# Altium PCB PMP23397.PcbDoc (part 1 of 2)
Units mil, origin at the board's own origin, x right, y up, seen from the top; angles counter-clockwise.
Board outline 1800 x 1800 mil, 2 copper layers (Top Layer, Bottom Layer), stack 62 mil thick; 47 components, 18 nets, 94 pads, 33 vias.
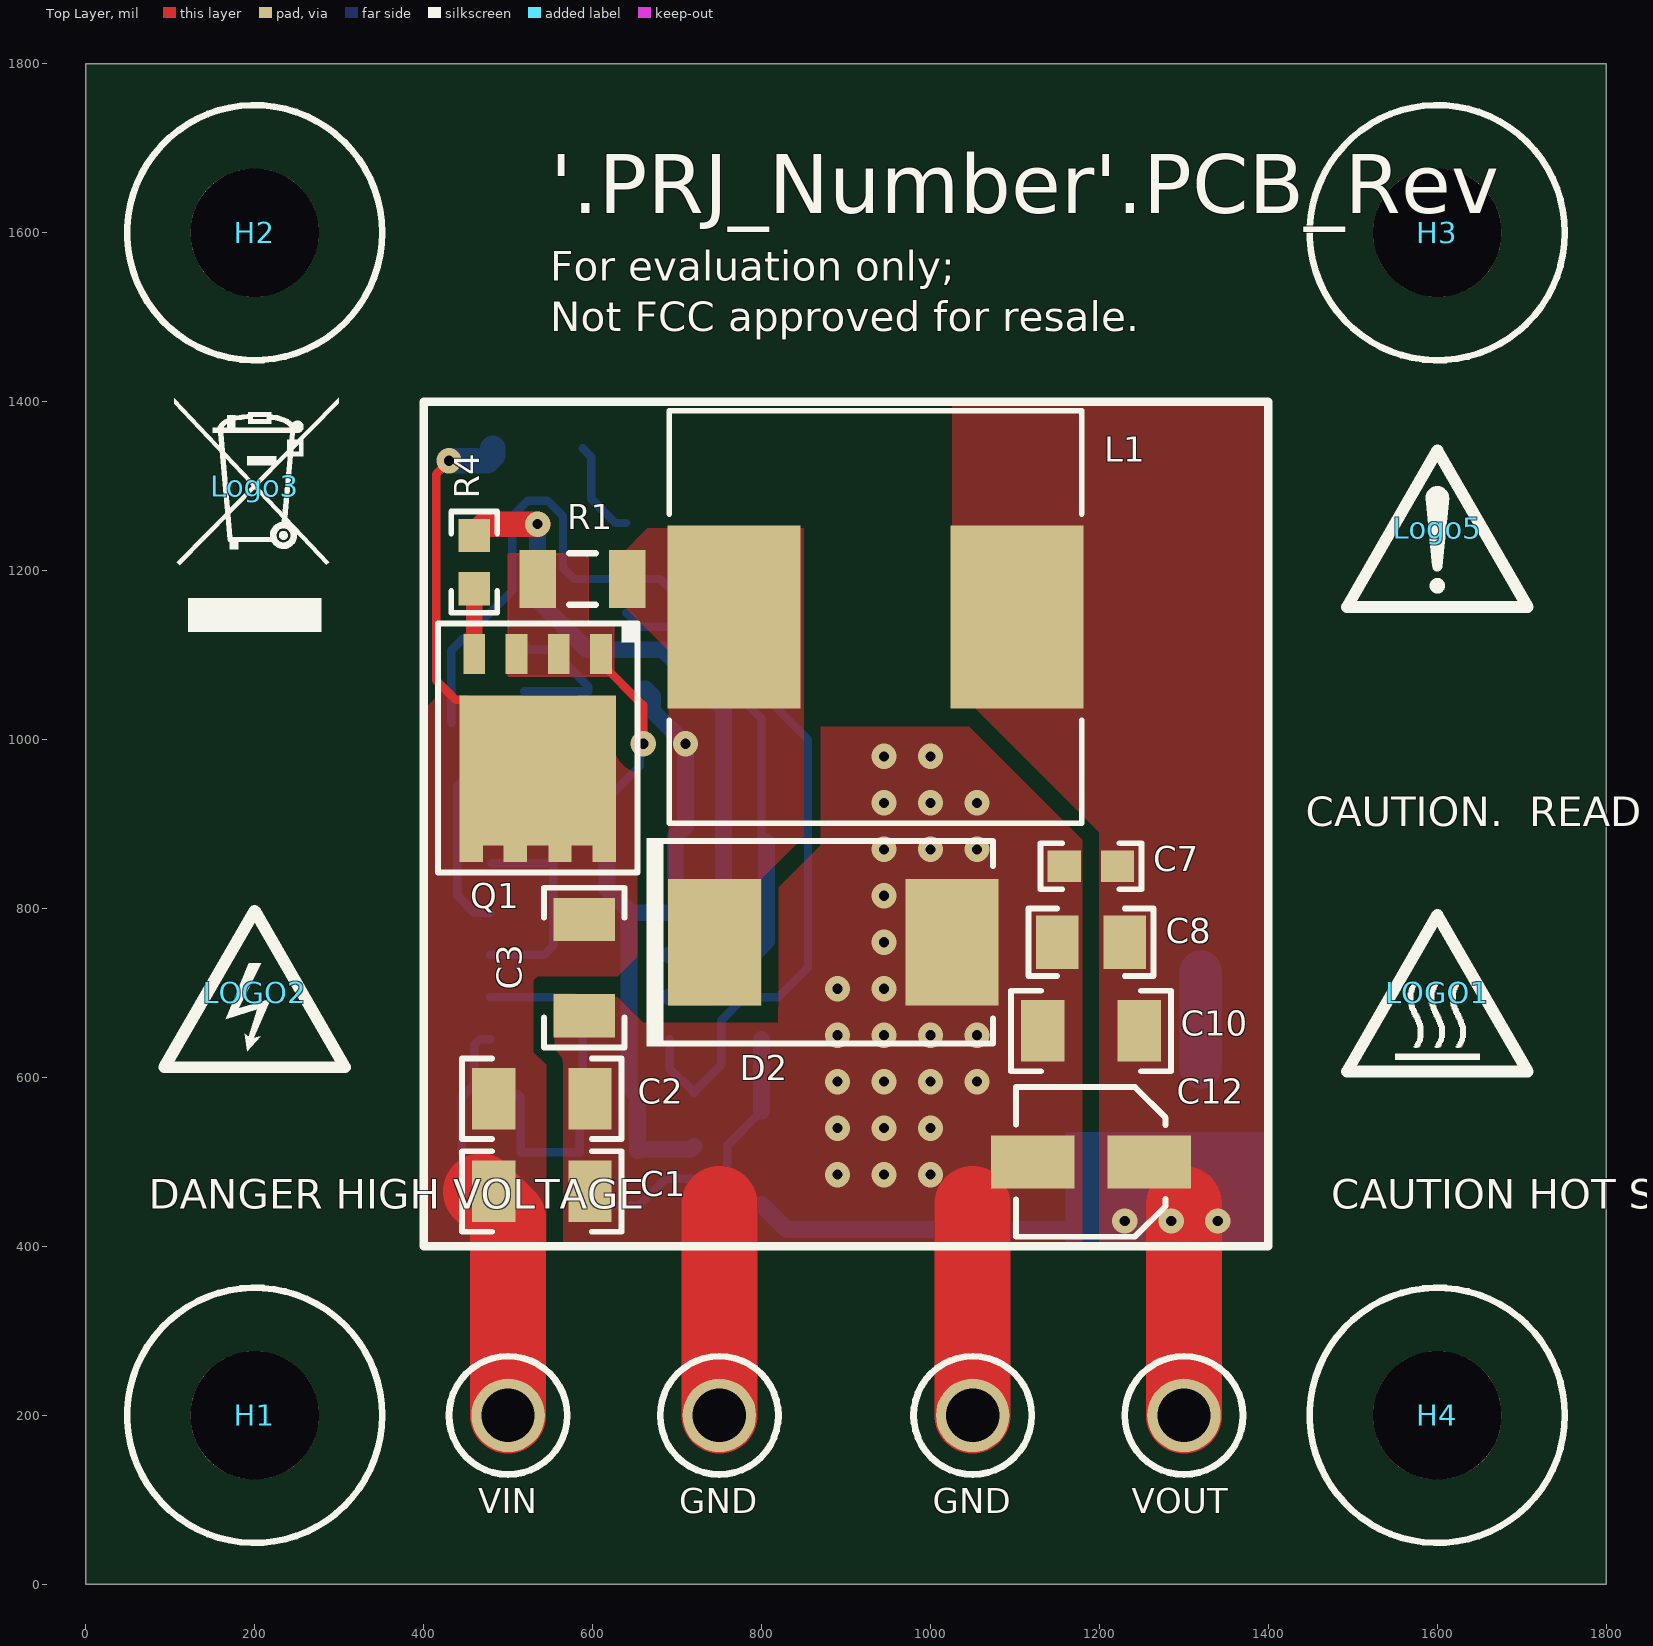
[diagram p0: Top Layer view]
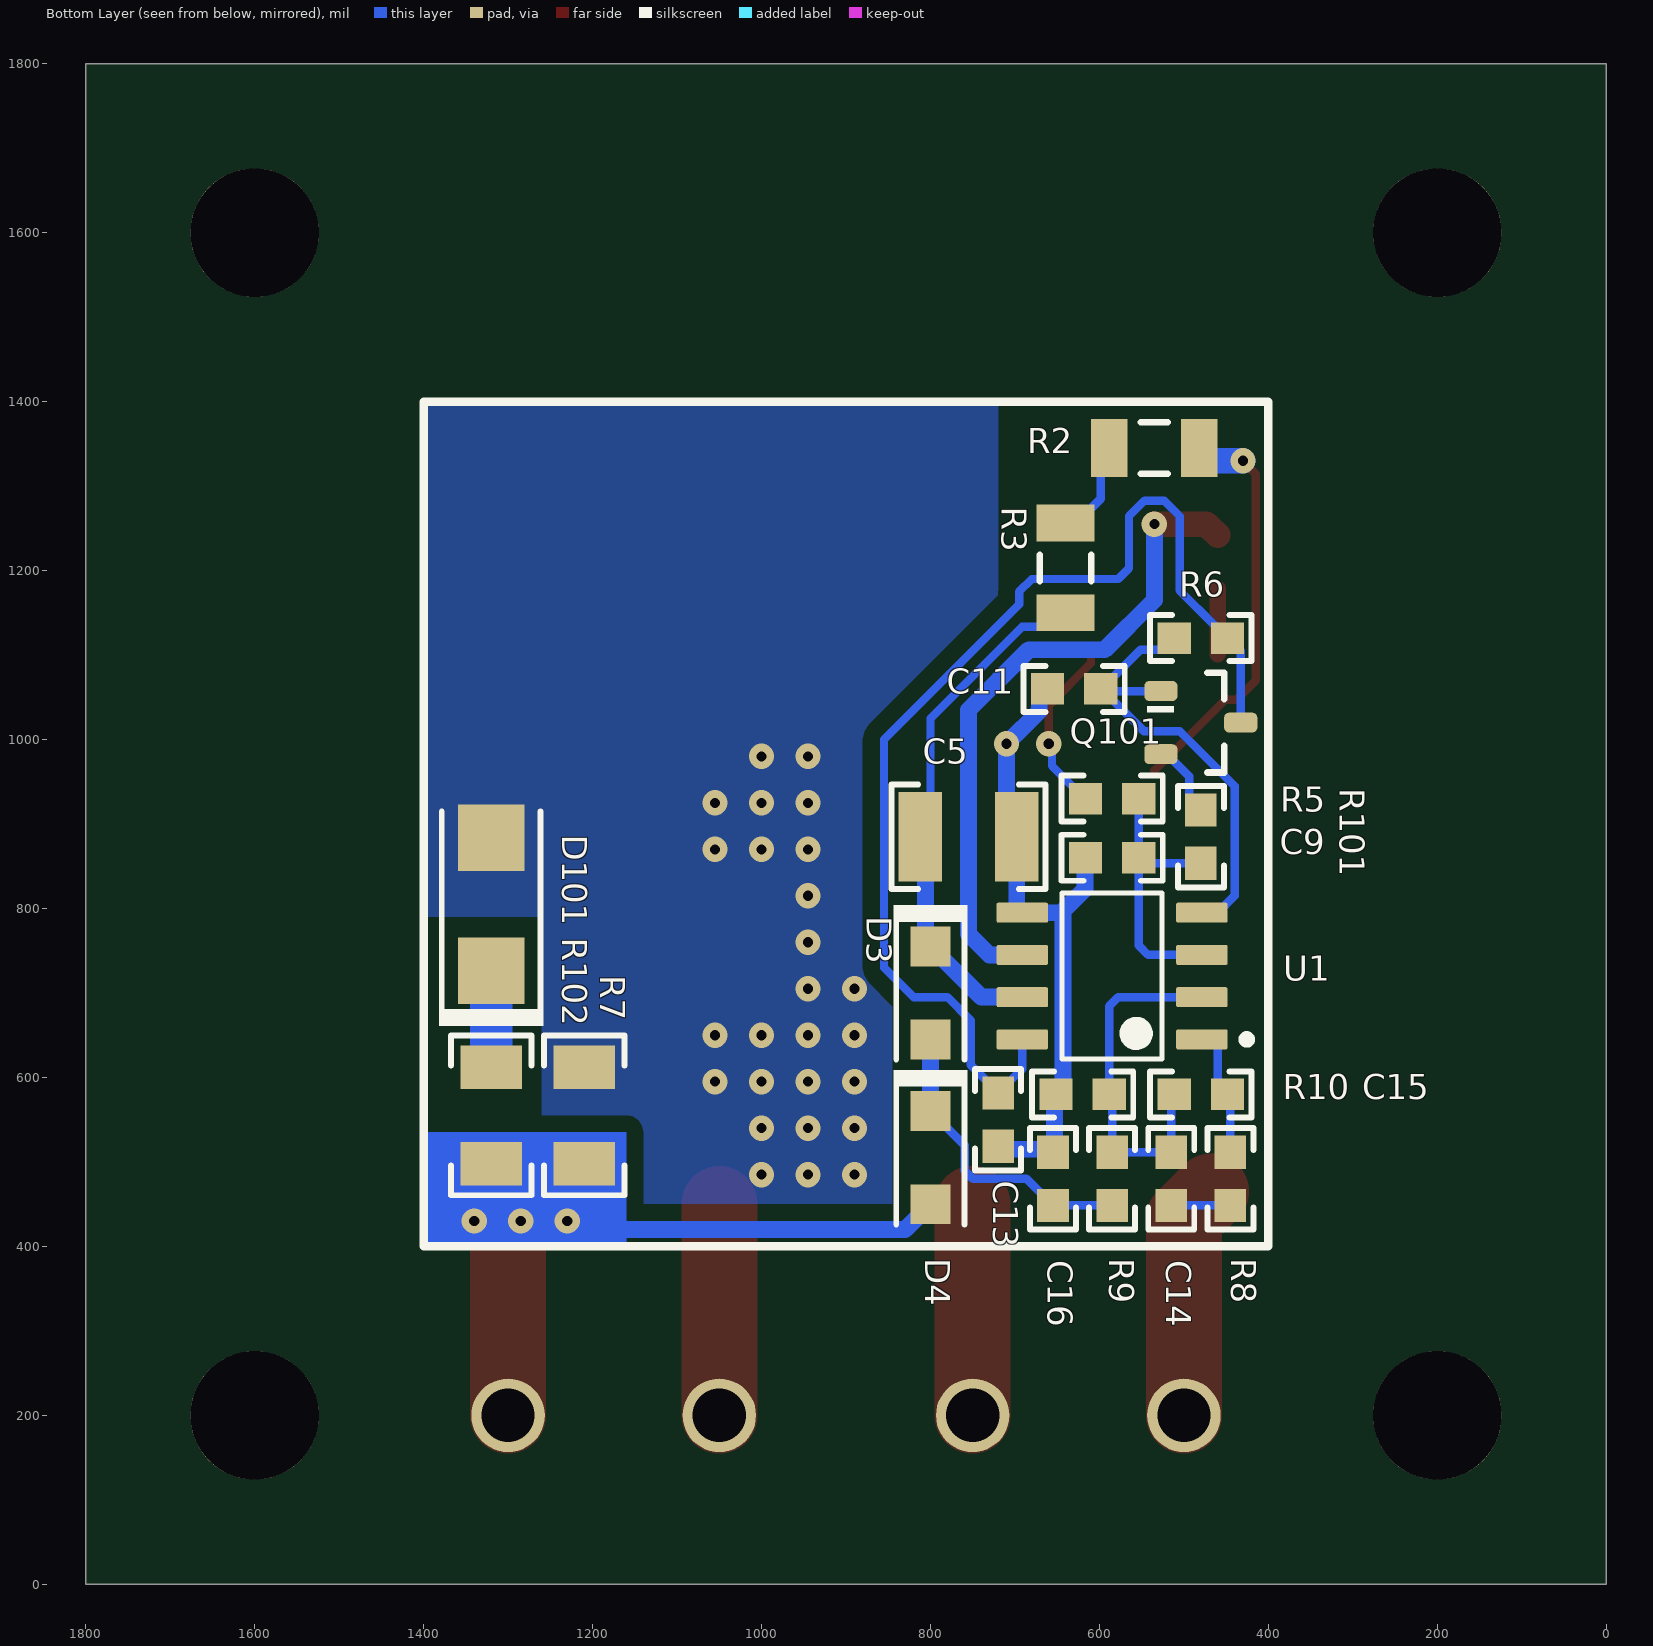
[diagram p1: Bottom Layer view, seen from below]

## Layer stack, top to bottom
Top Solder: solder mask 0.4, Solder Resist, Dk 3.5
Top Layer: signal copper 1.4
Dielectric1: core 59.2, FR-4 High Tg, Dk 4.8
Bottom Layer: signal copper 1.4
Bottom Solder: solder mask 0.4, Solder Resist, Dk 3.5

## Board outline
0,0 0,1800 1800,1800 1800,0

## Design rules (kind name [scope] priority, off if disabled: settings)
AcuteAngle [All] p1: minimum=4.50000000000000E+0001 checktracksonly=FALSE
AssemblyTestPointUsage [All] p1: valid=2
BoardOutlineClearance BoardOutlineClearance_MountingHoles [OnCopper and InComponentClass('Mounting Holes')] p1: gap=25 ignorepadtopadclearanceinfootprint=FALSE
BoardOutlineClearance BoardOutlineClearance_Poly [OnCopper and InPoly] p2: gap=25 ignorepadtopadclearanceinfootprint=FALSE
BoardOutlineClearance [OnCopper and Not InComponentClass('Logo') and not InComponentClass('FiducialMark') and not InRegion(1000,500,4000,800)] p3: gap=25 ignorepadtopadclearanceinfootprint=FALSE
Clearance Clearance_2 [InNetClass('HV') vs Not InNetClass('HV')] p1: gap=60 ignorepadtopadclearanceinfootprint=FALSE
Clearance Clearance_1 [InNetClass('MV') vs Not InNetClass('MV')] p2: gap=30 ignorepadtopadclearanceinfootprint=FALSE
Clearance Clearance_Keepouts [((IsTrack Or IsArc) And Not InPoly) And IsFree and IsKeepOut vs ((IsTrack Or IsArc) And Not InPoly) And IsFree and IsKeepOut] p3: gap=0 ignorepadtopadclearanceinfootprint=FALSE
Clearance Clearance_BoardEdge_MountingHoles [OnCopper and InComponentClass('Mounting Holes') vs IsKeepOut] p4: gap=40 ignorepadtopadclearanceinfootprint=FALSE except(0: Arc-Hole Track-Hole SMDPad-Hole THPad-Hole Via-Hole Fill-Hole Poly-Hole Region-Hole Text-Hole)
Clearance Clearance_BoardEdge_Poly [OnCopper and InPoly vs IsKeepOut] p5: gap=50 ignorepadtopadclearanceinfootprint=FALSE except(0: Arc-Hole Track-Hole SMDPad-Hole THPad-Hole Via-Hole Fill-Hole Poly-Hole Region-Hole Text-Hole)
Clearance Clearance_BoardEdge [OnCopper and Not InComponentClass('Logo') and not InComponentClass('FiducialMark') and not InRegion(1000,500,4000,800) and Not IsKeepout vs IsKeepOut] p6: gap=50 ignorepadtopadclearanceinfootprint=FALSE
Clearance Clearance_Poly [InPolygon] p7: gap=20 ignorepadtopadclearanceinfootprint=FALSE except(0: Arc-Hole Track-Hole SMDPad-Hole THPad-Hole Via-Hole Fill-Hole Poly-Hole Region-Hole Text-Hole)
Clearance [All] p8: gap=7.87 ignorepadtopadclearanceinfootprint=FALSE except(0: Arc-Hole Track-Hole SMDPad-Hole THPad-Hole Via-Hole Fill-Hole Poly-Hole Region-Hole Text-Hole)
ComponentClearance ComponentClearance_MountingHoles_FiducialMarks [InComponentClass('Mounting Holes') vs InComponentClass('FiducialMark')] p1: gap=20 collisioncheckmode=3 verticalgap=10 showdistances=FALSE
ComponentClearance ComponentClearance_Shunt [InComponentClass('Header') vs InComponentClass('Shunt')] p2: gap=0 collisioncheckmode=3 verticalgap=0 showdistances=FALSE
ComponentClearance ComponentClearance_Logo [InComponentClass('Logo')] p3: gap=5 collisioncheckmode=3 verticalgap=10 showdistances=FALSE
ComponentClearance ComponentClearance_ScrewToNut [(HasFootprint('NY PMS 440 0025 PH')) vs (HasFootprint('Keystone_1902C'))] p4: gap=20 collisioncheckmode=3 verticalgap=100000 showdistances=FALSE
ComponentClearance ComponentClearance_MountingHoles [InComponentClass('Mounting Holes')] p5: gap=20 collisioncheckmode=3 verticalgap=10 showdistances=FALSE
ComponentClearance ComponentClearance_SmallPassives [HasFootprint('0201*') or HasFootprint('0402*') or HasFootprint('0508') or HasFootprint('0603*') or HasFootprint('0612') or HasFootprint('0805*') or HasFootprint('0815*') or HasFootprint('0830*') or HasFootprint('1206*') or HasFootprint('1210*') or HasFootprint('1808*') or HasFootprint('1812*') or HasFootprint('1825*') or HasFootprint('2010*') or HasFootprint('2220*') or HasFootprint('2225*') or HasFootprint('2512*') or HasFootprint('2728*') or HasFootprint('3518*') vs HasFootprint('0201*') or HasFootprint('0402*') or HasFootprint('0508') or HasFootprint('0603*') or HasFootprint('0612') or HasFootprint('0805*') or HasFootprint('0815*') or HasFootprint('0830*') or HasFootprint('1206*') or HasFootprint('1210*') or HasFootprint('1808*') or HasFootprint('1812*') or HasFootprint('1825*') or HasFootprint('2010*') or HasFootprint('2220*') or HasFootprint('2225*') or HasFootprint('2512*') or HasFootprint('2728*') or HasFootprint('3518*')] p6: gap=20 collisioncheckmode=3 verticalgap=20 showdistances=FALSE
ComponentClearance ComponentClearance_THtoSMT [IsThruComponent vs IsSMTComponent] p7: gap=10 collisioncheckmode=3 verticalgap=10 showdistances=FALSE
ComponentClearance ComponentClearance_THtoTH [IsThruComponent vs IsThruComponent] p8: gap=10 collisioncheckmode=3 verticalgap=10 showdistances=FALSE
ComponentClearance [All] p9: gap=10 collisioncheckmode=3 verticalgap=10 showdistances=FALSE
DiffPairsRouting [All] p1: maxlimit=100 minlimit=10 mostfreqgap=10 toplayer_minwidth=15 toplayer_maxwidth=15 toplayer_prefwidth=15 bottomlayer_minwidth=15 bottomlayer_maxwidth=15 bottomlayer_prefwidth=15 maxuncoupledlength=1000
FabricationTestPointUsage TestPointUsage [All] p1: valid=2 allowmultiple=FALSE
FabricationTestpoint Testpoint [All] p1: side=3 testpointundercomponent=TRUE minsize=40 maxsize=100 preferedsize=60 minholesize=0 maxholesize=40 preferedholesize=32 testpointgrid=1 allowsidetop=TRUE allowsidebottom=TRUE usegrid=TRUE gridtolerance=0.01
FanoutControl Fanout_LCC [IsLCC] p1: bgadir=Out bgaviamode=Centered fanoutstyle=Auto fanoutdirection=Alternating viagrid=1 // Fanout_LCC (Default Rule)
FanoutControl Fanout_BGA [IsBGA] p2: bgadir=Out bgaviamode=Centered fanoutstyle=Auto fanoutdirection=Alternating viagrid=1 // Fanout_BGA (Default Rule)
FanoutControl Fanout_Default [All] p4: bgadir=Out bgaviamode=Centered fanoutstyle=Auto fanoutdirection=Alternating viagrid=1 // Fanout_Default (Default Rule)
FanoutControl Fanout_Small [(CompPinCount < 5)] p5: bgadir=Out bgaviamode=Centered fanoutstyle=Auto fanoutdirection=OutThenIn viagrid=1 // Fanout_Small (Default Rule)
Height [All] p1: minheight=0 maxheight=3000 prefheight=500
HoleSize [All] p1: absolutevalues=TRUE maxlimit=251 minlimit=7.87 maxpercent=80.000 minpercent=20.000
MinimumAnnularRing MinimumAnnularRing_ThermalPadVias [IsVia and InAnyComponent] p1: minimumring=5.91
MinimumAnnularRing [All] p2: minimumring=8
MinimumSolderMaskSliver MinimumSolderMaskSliver_Logo [InComponentClass('Logo') vs InComponentClass('Logo')] p1: minsoldermaskwidth=0.7
MinimumSolderMaskSliver [All] p2: minsoldermaskwidth=3.94
PlaneConnect [All] p1: planeconnectstyle=Direct reliefexpansion=10 reliefentries=4 reliefconductorwidth=10 reliefairgap=10
PolygonConnect PolygonConnect_15 [All vs IsNamedPolygon('C109_2') Or  IsNamedPolygon('C107_2') Or  IsNamedPolygon('HV') Or  IsNamedPolygon('Q203_5') Or  IsNamedPolygon('C107_2') Or  IsNamedPolygon('HS') Or  IsNamedPolygon('Q201_5') Or  IsNamedPolygon('Q203_5') Or  IsNamedPolygon('C106_2') Or  IsNamedPolygon('C108_2') Or  IsNamedPolygon('Vout') Or  IsNamedPolygon('Q203_5') Or  IsNamedPolygon('C108_2') Or  IsNamedPolygon('C113_2') Or  IsNamedPolygon('Q203_5') Or  IsNamedPolygon('Q201_5') Or  IsNamedPolygon('C107_2') Or  IsNamedPolygon('C102_1') Or  IsNamedPolygon('SGND') Or  IsNamedPolygon('GND') Or  IsNamedPolygon('SGND') Or  IsNamedPolygon('GND') Or  IsNamedPolygon('IN+') Or  IsNamedPolygon('IN+') Or  IsNamedPolygon('Q201_5') Or  IsNamedPolygon('Q201_5') Or  IsNamedPolygon('SGND') Or  IsNamedPolygon('SGND') Or  IsNamedPolygon('Vout') Or  IsNamedPolygon('Vout') Or  IsNamedPolygon('IN+') Or  IsNamedPolygon('GND') Or  IsNamedPolygon('IN+') Or  IsNamedPolygon('GND')] p1: connectstyle=Direct reliefconductorwidth=10 reliefentries=4 polygonreliefangle="90 Angle" airgapwidth=10
PolygonConnect PolygonConnect_14 [All vs IsNamedPolygon('C106_2') Or  IsNamedPolygon('C107_2') Or  IsNamedPolygon('C107_2') Or  IsNamedPolygon('C107_2') Or  IsNamedPolygon('C102_1') Or  IsNamedPolygon('Q203_5') Or  IsNamedPolygon('Vout') Or  IsNamedPolygon('Q203_5') Or  IsNamedPolygon('Q203_5') Or  IsNamedPolygon('Q201_5') Or  IsNamedPolygon('C108_2') Or  IsNamedPolygon('Q203_5') Or  IsNamedPolygon('HS') Or  IsNamedPolygon('HV') Or  IsNamedPolygon('C108_2') Or  IsNamedPolygon('Q201_5') Or  IsNamedPolygon('C109_2') Or  IsNamedPolygon('Q201_5') Or  IsNamedPolygon('Q201_5') Or  IsNamedPolygon('C113_2')] p2: connectstyle=Direct reliefconductorwidth=10 reliefentries=4 polygonreliefangle="90 Angle" airgapwidth=10
PolygonConnect PolygonConnect_13 [All vs IsNamedPolygon('C102_1') Or  IsNamedPolygon('HV') Or  IsNamedPolygon('C107_2') Or  IsNamedPolygon('C109_2') Or  IsNamedPolygon('C107_2') Or  IsNamedPolygon('C108_2') Or  IsNamedPolygon('C106_2') Or  IsNamedPolygon('C108_2') Or  IsNamedPolygon('C113_2') Or  IsNamedPolygon('C107_2')] p3: connectstyle=Direct reliefconductorwidth=10 reliefentries=4 polygonreliefangle="90 Angle" airgapwidth=10
PolygonConnect PolygonConnect_12 [All vs IsNamedPolygon('C107_2') Or  IsNamedPolygon('C113_2') Or  IsNamedPolygon('C106_2') Or  IsNamedPolygon('C107_2') Or  IsNamedPolygon('C107_2') Or  IsNamedPolygon('C102_1')] p4: connectstyle=Direct reliefconductorwidth=10 reliefentries=4 polygonreliefangle="90 Angle" airgapwidth=10
PolygonConnect PolygonConnect_11 [All vs IsNamedPolygon('C106_2') Or  IsNamedPolygon('C102_1') Or  IsNamedPolygon('C107_2') Or  IsNamedPolygon('C107_2') Or  IsNamedPolygon('C107_2')] p5: connectstyle=Direct reliefconductorwidth=10 reliefentries=4 polygonreliefangle="90 Angle" airgapwidth=10
PolygonConnect PolygonConnect_10 [All vs IsNamedPolygon('C106_2')] p6: connectstyle=Direct reliefconductorwidth=10 reliefentries=4 polygonreliefangle="90 Angle" airgapwidth=10
PolygonConnect PolygonConnect_9 [All vs IsNamedPolygon('C11_1') Or  IsNamedPolygon('Vin') Or  IsNamedPolygon('Vin') Or  IsNamedPolygon('5V') Or  IsNamedPolygon('D6_2') Or  IsNamedPolygon('Q3_3') Or  IsNamedPolygon('GND2') Or  IsNamedPolygon('GND2') Or  IsNamedPolygon('GND') Or  IsNamedPolygon('Q3_4') Or  IsNamedPolygon('12V5') Or  IsNamedPolygon('GND') Or  IsNamedPolygon('12V5') Or  IsNamedPolygon('D3_1')] p7: connectstyle=Direct reliefconductorwidth=10 reliefentries=4 polygonreliefangle="90 Angle" airgapwidth=10
PolygonConnect PolygonConnect_8 [All vs IsNamedPolygon('C11_1') Or  IsNamedPolygon('Vin') Or  IsNamedPolygon('12V5') Or  IsNamedPolygon('Q3_3') Or  IsNamedPolygon('GND2') Or  IsNamedPolygon('GND2') Or  IsNamedPolygon('5V') Or  IsNamedPolygon('Q3_4') Or  IsNamedPolygon('12V5')] p8: connectstyle=Direct reliefconductorwidth=10 reliefentries=4 polygonreliefangle="90 Angle" airgapwidth=10
PolygonConnect PolygonConnect_7 [All vs IsNamedPolygon('GND2') Or  IsNamedPolygon('GND2') Or  IsNamedPolygon('5V') Or  IsNamedPolygon('12V5') Or  IsNamedPolygon('12V5') Or  IsNamedPolygon('C11_1')] p9: connectstyle=Direct reliefconductorwidth=10 reliefentries=4 polygonreliefangle="90 Angle" airgapwidth=10
PolygonConnect PolygonConnect_6 [All vs IsNamedPolygon('GND2') Or  IsNamedPolygon('SGND') Or  IsNamedPolygon('GND1') Or  IsNamedPolygon('C901_1') Or  IsNamedPolygon('SGND') Or  IsNamedPolygon('GND2') Or  IsNamedPolygon('GND1')] p10: connectstyle=Direct reliefconductorwidth=10 reliefentries=4 polygonreliefangle="90 Angle" airgapwidth=10
PolygonConnect PolygonConnect_5 [All vs IsNamedPolygon('GND1') Or  IsNamedPolygon('GND1')] p11: connectstyle=Direct reliefconductorwidth=10 reliefentries=4 polygonreliefangle="90 Angle" airgapwidth=10
PolygonConnect PolygonConnect_4 [All vs IsNamedPolygon('C21_1') Or  IsNamedPolygon('C5_1') Or  IsNamedPolygon('C12_2') Or  IsNamedPolygon('C2_2') Or  IsNamedPolygon('C13_1') Or  IsNamedPolygon('C28_1') Or  IsNamedPolygon('C6_1') Or  IsNamedPolygon('GND') Or  IsNamedPolygon('GND2') Or  IsNamedPolygon('C14_1') Or  IsNamedPolygon('C13_1') Or  IsNamedPolygon('Q1_3') Or  IsNamedPolygon('C14_1') Or  IsNamedPolygon('C5_1') Or  IsNamedPolygon('GND2') Or  IsNamedPolygon('C28_1') Or  IsNamedPolygon('D5_2') Or  IsNamedPolygon('D6_2') Or  IsNamedPolygon('D2_1') Or  IsNamedPolygon('C12_2') Or  IsNamedPolygon('D2_1') Or  IsNamedPolygon('C4_1') Or  IsNamedPolygon('C4_1') Or  IsNamedPolygon('C2_2') Or  IsNamedPolygon('GND') Or  IsNamedPolygon('C33_1') Or  IsNamedPolygon('C9_1')] p12: connectstyle=Direct reliefconductorwidth=10 reliefentries=4 polygonreliefangle="90 Angle" airgapwidth=10
PolygonConnect PolygonConnect_3 [All vs IsNamedPolygon('C28_1') Or  IsNamedPolygon('C12_2') Or  IsNamedPolygon('C28_1') Or  IsNamedPolygon('C9_1') Or  IsNamedPolygon('D5_2') Or  IsNamedPolygon('C12_2') Or  IsNamedPolygon('C2_2') Or  IsNamedPolygon('C14_1') Or  IsNamedPolygon('C4_1') Or  IsNamedPolygon('C14_1') Or  IsNamedPolygon('D6_2') Or  IsNamedPolygon('GND2') Or  IsNamedPolygon('Q1_3') Or  IsNamedPolygon('C5_1') Or  IsNamedPolygon('D2_1') Or  IsNamedPolygon('C4_1') Or  IsNamedPolygon('C13_1') Or  IsNamedPolygon('C5_1') Or  IsNamedPolygon('C13_1') Or  IsNamedPolygon('C33_1') Or  IsNamedPolygon('D2_1') Or  IsNamedPolygon('GND') Or  IsNamedPolygon('GND') Or  IsNamedPolygon('GND2') Or  IsNamedPolygon('C2_2') Or  IsNamedPolygon('C6_1') Or  IsNamedPolygon('C21_1')] p13: connectstyle=Direct reliefconductorwidth=10 reliefentries=4 polygonreliefangle="90 Angle" airgapwidth=10
PolygonConnect PolygonConnect_2 [All vs IsNamedPolygon('C21_1') Or  IsNamedPolygon('C4_1') Or  IsNamedPolygon('D5_2') Or  IsNamedPolygon('C5_1') Or  IsNamedPolygon('C14_1') Or  IsNamedPolygon('C13_1') Or  IsNamedPolygon('C4_1') Or  IsNamedPolygon('C33_1') Or  IsNamedPolygon('C12_2') Or  IsNamedPolygon('D2_1') Or  IsNamedPolygon('C2_2') Or  IsNamedPolygon('C28_1') Or  IsNamedPolygon('C12_2') Or  IsNamedPolygon('D2_1') Or  IsNamedPolygon('C5_1') Or  IsNamedPolygon('Q1_3') Or  IsNamedPolygon('GND') Or  IsNamedPolygon('D6_2') Or  IsNamedPolygon('C6_1') Or  IsNamedPolygon('C2_2') Or  IsNamedPolygon('C14_1') Or  IsNamedPolygon('C28_1') Or  IsNamedPolygon('C13_1') Or  IsNamedPolygon('C9_1') Or  IsNamedPolygon('GND')] p14: connectstyle=Direct reliefconductorwidth=10 reliefentries=4 polygonreliefangle="90 Angle" airgapwidth=10
PolygonConnect PolygonConnect_1 [All vs IsNamedPolygon('C28_1') Or  IsNamedPolygon('D5_2') Or  IsNamedPolygon('C5_1') Or  IsNamedPolygon('C5_1') Or  IsNamedPolygon('D2_1') Or  IsNamedPolygon('C21_1') Or  IsNamedPolygon('C9_1') Or  IsNamedPolygon('C4_1') Or  IsNamedPolygon('C14_1') Or  IsNamedPolygon('C28_1') Or  IsNamedPolygon('C6_1') Or  IsNamedPolygon('C12_2') Or  IsNamedPolygon('C33_1') Or  IsNamedPolygon('C4_1') Or  IsNamedPolygon('C13_1') Or  IsNamedPolygon('C12_2') Or  IsNamedPolygon('D6_2') Or  IsNamedPolygon('C2_2') Or  IsNamedPolygon('C14_1') Or  IsNamedPolygon('D2_1') Or  IsNamedPolygon('C2_2') Or  IsNamedPolygon('C13_1')] p15: connectstyle=Direct reliefconductorwidth=10 reliefentries=4 polygonreliefangle="90 Angle" airgapwidth=10
PolygonConnect [All] p16: connectstyle=Direct reliefconductorwidth=10 reliefentries=4 polygonreliefangle="90 Angle" airgapwidth=10
RoutingVias ThermalPadVias [IsVia and InAnyComponent] p1: holewidth=7.87 width=19.68 viastyle="Through Hole" minholewidth=7.87 minwidth=19.68 maxholewidth=12.99 maxwidth=23.62
RoutingVias [All] p2: holewidth=16 width=34 viastyle="Through Hole" minholewidth=7.87 minwidth=20 maxholewidth=40 maxwidth=65
SilkToBoardRegionClearance [Not ((IsComment or IsDesignator) And (Hide <> 'False')) and not InRegion(1000,500,4000,800)] p1:
SilkToSilkClearance SilkToSilkClearance_Pb-FreeLogo [(HasFootprint('Pb-Free_Overlay_Medium') OR HasFootprint('Pb-Free_Overlay_Small')) vs (HasFootprint('Pb-Free_Overlay_Medium') OR HasFootprint('Pb-Free_Overlay_Small'))] p1: silktosilkclearance=0
SilkToSilkClearance [All] p2: silktosilkclearance=4
SilkToSolderMaskClearance SilkToComponentPadClearance [IsPad and InAnycomponent] p1: minsilkscreentomaskgap=5 clearancetoexposedcopper=TRUE
SilkToSolderMaskClearance "Silk to Solder Mask Opening" [All] p2: minsilkscreentomaskgap=4 clearancetoexposedcopper=FALSE
SolderMaskExpansion [All] p1: expansion=1.97 istentingtop=FALSE
Width [All] p1: maxlimit=100 minlimit=6 preferedwidth=10 checkconnectedcopper=TRUE
14 further rules are at their usual default settings.

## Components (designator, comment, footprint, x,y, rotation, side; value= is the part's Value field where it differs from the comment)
C1 "CGA5L3X7T2E224K160AE" 1206 540,465 r0 top value=0.22uF
C2 "CGA5L3X7T2E224K160AE" 1206 540,575 r0 top value=0.22uF
C3 "CGA5L3X7T2E224K160AE" 1206 590,730 r270 top value=0.22uF
C5 "GRM32ER61E226KE15L" 1210_270 755,885 r180 bottom value=22uF
C7 "GRM188R71E224KA88D" 0603 1190,850 r180 top value=0.22uF
C8 "GRM21BR71E225KA73L" 0805_HV 1190,760 r180 top value=2.2uF
C9 "GRM1885C1H101JA01D" 0603 585,860 r180 bottom value=100pF
C10 "GRM31CR71E106MA12L" 1206 1190,655 r180 top value=10uF
C11 "GRM188R71E222KA01D" 0603 630,1060 r0 bottom value=2200pF
C12 "EEE-FK1C220UR" SM_RADIAL_B 1190,500 r180 top value=22uF
C13 "GRM188R71E224KA88D" 0603 720,550 r270 bottom value=0.22uF
C14 "GRM188R71E224KA88D" 0603 515,480 r270 bottom value=0.22uF
C15 "GRM188R71E222KA01D" 0603 480,580 r0 bottom value=2200pF
C16 "GRM188R71E224KA88D" 0603 655,480 r270 bottom value=0.22uF
D2 "ES3G-E3/57T" SMC 885,760 r0 top value=400V
D3 "BAS21H,115" SOD-123F 800,700 r270 bottom value=200V
D4 "BAS21H,115" SOD-123F 800,505 r270 bottom value=200V
D101 "SMAJ14A" SMA 1320,805 r90 bottom value=14V
GND "5011" Keystone5011 1050,200 r0 top
GND "5011" Keystone5011 750,200 r0 top
H1 "4824" KEYSTONE_4824 200,200 r0 top
H2 "4824" KEYSTONE_4824 200,1600 r0 top
H3 "4824" KEYSTONE_4824 1600,1600 r0 top
H4 "4824" KEYSTONE_4824 1600,200 r0 top
L1 "MSS1278H-684KLB" MSS1278 935,1145 r0 top value=680uH
LOGO1 "CAUTION HOT SURFACE" IEC_HotSurface_Small 1600,700 r0 top
LOGO2 "DANGER HIGH VOLTAGE" IEC_HighVoltage_Small 200,700 r0 top
Logo3 "WEEE logo" WEEE_Minimum 200,1300 r0 top
Logo4 "FCC disclaimer" FCC_disclaimer 990,2010 r0 top
Logo5 "CAUTION.  READ USER GUIDE BEFORE USE" IEC_Caution_Small 1600,1250 r0 top
Q1 "BSC16DN25NS3 G" PG-TDSON-8 535,990 r270 top value=250V
Q101 "MMBT2222A" SOT-23 480,1020 r180 bottom value="40 V"
R1 "CRCW12061R00FKEA" 1206L 588.15,1190 r180 top value=1.00
R2 "CRCW120620K0JNEA" 1206L 535,1345 r0 bottom value=20k
R3 "CRCW120620K0JNEA" 1206L 640,1203.15 r270 bottom value=20k
R4 "CRCW06034R70JNEA" 0603 460,1210 r90 top value=4.7
R5 "CRCW06033K01FKEA" 0603 585,930 r180 bottom value=3.01k
R6 "CRCW060310K0FKEA" 0603 480,1120 r180 bottom value=10.0k
R7 "CRCW12064K70JNEA" 1206 1210,555 r270 bottom value=4.7k
R8 "CRCW06032K49FKEA" 0603 445,480 r270 bottom value=2.49k
R9 "CRCW060310K0FKEA" 0603 585,480 r270 bottom value=10.0k
R10 "CRCW06032K49FKEA" 0603 620,580 r180 bottom value=2.49k
R101 "CRCW060310K0FKEA" 0603 480,885 r270 bottom value=10.0k
R102 "CRCW1206100RJNEA" 1206 1320,555 r270 bottom value=100
U1 "UCC28C52DR" D0008A-MFG 585,720 r0 bottom
VIN "5010" Keystone5010 500,200 r0 top
VOUT "5010" Keystone5010 1300,200 r0 top

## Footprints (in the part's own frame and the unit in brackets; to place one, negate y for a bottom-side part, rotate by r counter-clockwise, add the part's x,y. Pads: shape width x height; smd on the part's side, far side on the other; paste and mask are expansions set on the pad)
0603 [mm] "0603 from SM-752 data"
  rect 1x0.95 smd: 1(-0.8,0) 2(0.8,0)
  silkscreen extent -1.52,-0.69 1.52,0.69, body extent -0.87,-0.47 0.87,0.47, height 1
0805_HV [mil] "0805 with 30mil clearance between pads"
  rect 50x63 smd: 1(-40,0) 2(40,0)
  silkscreen extent -74,-40 74,40, body extent -43,-29 43,29, height 57
1206 [mm] "1206 from SM-752 data"
  rect 1.3x1.85 smd: 1(-1.45,0) 2(1.45,0)
  silkscreen extent -2.4,-1.21 2.4,1.21, body extent -1.7,-0.9 1.7,0.9, height 1.35
1206L [mm] "1206 from SM-752 data"
  rect 1.1x1.75 smd: 1(-1.35,0) 2(1.35,0)
  silkscreen extent -0.4,-0.77 0.4,0.77, body extent -1.7,-0.9 1.7,0.9, height 1.35
1210_270 [mm] "1210"
  rect 1.3x2.7 smd: 1(-1.45,0) 2(1.45,0)
  silkscreen extent -2.32,-1.57 2.32,1.57, body extent -1.7,-1.35 1.7,1.35, height 2.7
D0008A-MFG [mm]
  rrect17% 1.55x0.6 smd paste+0 mask+0: 1(-2.7,1.905) 2(-2.7,0.635) 3(-2.7,-0.635) 4(-2.7,-1.905) 5(2.7,-1.905) 6(2.7,-0.635) 7(2.7,0.635) 8(2.7,1.905)
  silkscreen extent -4.17,-2.5 1.5,2.5, body extent -3,-2.45 3,2.45, height 1.75
FCC_disclaimer [mil]
IEC_Caution_Small [mil]
  silkscreen extent -107,-93 107,92
IEC_HighVoltage_Small [mil]
  silkscreen extent -107,-88 107,97
IEC_HotSurface_Small [mil]
  silkscreen extent -107,-93 107,92
Keystone5010 [mil] "Keystone Multipurpose loops"
  round 87 hole 63: 1(0,0)
  silkscreen extent -70,-70 70,70, body extent -63,-63 63,62, height 319
Keystone5011 [mil] "Keystone Multipurpose loops"
  round 87 hole 63: 1(0,0)
  silkscreen extent -70,-70 70,70, body extent -63,-63 63,62, height 319
KEYSTONE_4824 [mil] "HEX STANDOFF 6-32 NYLON 1-1/2\""
  round 1 on Mech3: 0(0,0)
  round 152 hole 152 unplated: MH(0,0)
  silkscreen extent -151,-151 151,151, body extent -144,-125 144,125, height 1500
MSS1278 [mm] "Coilcraft recommended land pattern.  Document 598-2 rev 04/04/13"
  rect 4x5.5 smd: 1(-4.25,0) 2(4.25,0)
  silkscreen extent -6.2,-6.2 6.2,6.2, body extent -6.15,-6.15 6.15,6.15, height 8.05
PG-TDSON-8 [mm] "Infineon recommended land pattern"
  rect 1.2x0.65 smd: 1(-2.825,1.905) 2(-2.825,0.635) 3(-2.825,-0.635) 4(-2.825,-1.905)
  rect 0.5x0.7 smd: 5(3.175,-2) 6(3.175,-0.675) 7(3.175,0.675) 8(3.175,2)
  rect 4.5x4.7 smd paste-2.25: 9(0.675,0)
  silkscreen extent -3.74,-3 3.74,3, body extent -3.18,-2.89 3.18,2.9, height 1.1
SM_RADIAL_B [mm] "4 x 5.8mm:  Panasonic B"
  rect 2.5x1.6 smd: 1(-1.75,0) 2(1.75,0)
  silkscreen extent -2.24,-2.25 2.25,2.25, body extent -2.25,-2.25 2.25,2.25, height 6.1
SMA [mm] "Molded Diode, 2-Leads, Body 4.3x2.6mm, IPC Medium Density, based on OnSemi component dimensions and land pattern"
  rect 2x2 smd: 1(-2,0) 2(2,0)
  silkscreen extent -3.66,-1.57 2.79,1.57, body extent -2.6,-1.3 2.6,1.3, height 2.42
SMC [mil] "Molded Diode, 2-Leads, Body 6.9x5.8mm, IPC Medium Density, based on OnSemi component dimensions and land patterns"
  rect 110x150 smd: 1(-140.49,0) 2(140.49,0)
  silkscreen extent -221,-124 189,123, body extent -156,-116 156,116, height 91
SOD-123F [mm] "NXP recommended land pattern"
  rect 1.2x1.2 smd paste-0.05: 1(-1.4,0) 2(1.4,0)
  silkscreen extent -2.64,-1.12 2.01,1.12, body extent -1.8,-0.85 1.8,0.85, height 1.2
SOT-23 [mm] "SOT23, 3-Leads, Body 2.9x1.3mm, Pitch 0.95mm, Lead Span 2.5mm, IPC Medium Density"
  rrect50% 1x0.6 smd: 1(-1.2,0.95) 2(-1.2,-0.95) 3(1.2,0)
  silkscreen extent -1.63,-1.5 0.7,1.5, body extent -1.16,-1.45 1.21,1.45, height 1
WEEE_Minimum [mil] "WEEElie bin"
  silkscreen extent -95,-172 99,104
